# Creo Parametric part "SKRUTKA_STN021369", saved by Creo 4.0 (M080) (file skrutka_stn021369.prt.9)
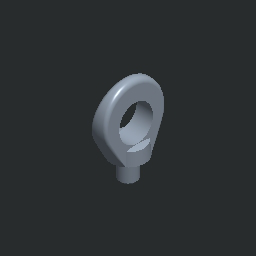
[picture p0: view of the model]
Units: Custom; MM, KILOGRAM, SECS
Materials in the file: OCEL, OCEL_N

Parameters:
  PTC_MATERIAL_NAME = "OCEL"
  NAZOV = "SKRUTKA_STN021369"
  NORMA = "STN 02 1369"

Other parameters: HMOTNOST, HUSTOTA, D25, D30, D26, D29, D31, D24, D40, D3, D21, D4, D2, D12

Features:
  1. datum plane "DTM1"
  2. protrusion
  3. datum plane "DTM3"
  4. cut
  5. datum plane "DTM4"
  6. cut
  7. round
  8. round
  9. protrusion
  10. chamfer
  11. datum plane "DTM7"
  12. datum plane "DTM8"

Other named items: THRU

Layers: 1, 2, 3, 4, 5, 6, 7, 8, 9, 10, 11, 12, 13, 14, 15, 16, 17, 18, 19, 20, 21, 22, 23, 24, 25, 26, 27, 28, 29, 30, 31, 32

Family table entries: GENERIC, SKRUTKA_M8, SKRUTKA_STN021369, value(d_val), 2/C, 2/&, 2/9, 2/4, 2/$, 2/F, 2/6, 2/ , 2/(, value(i_val), SKRUTKA_M10, SKRUTKA_STN021369, !/$, 2/C, 2/*, 2/9, 2/4, 2/$, 2/F, 2/6, 2/ , 2/(, SKRUTKA_M12, SKRUTKA_STN021369, !/(, 2/C, 2/0, 2/9, 2/4, 2/$, 2/F, 2/6, 2/ , 2/(, SKRUTKA_M16, SKRUTKA_STN021369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

Surfaces: 8 fillet, 7 plane, 7 cylinder, 5 cone, 3 torus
